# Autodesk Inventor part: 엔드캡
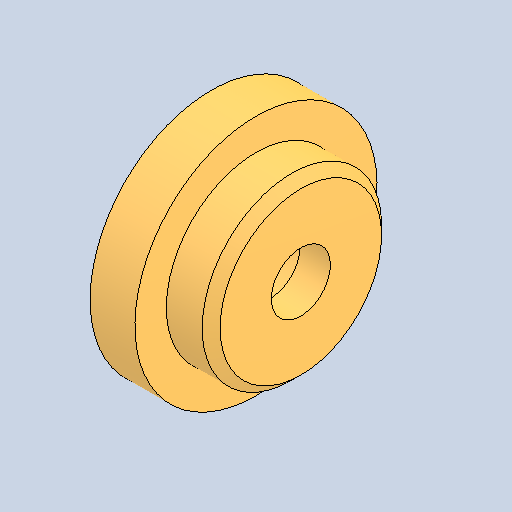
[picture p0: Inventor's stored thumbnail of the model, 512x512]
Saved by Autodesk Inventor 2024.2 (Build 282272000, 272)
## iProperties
Created: 2026-01
Part Number: 엔드캡
Material: 강철, 연강
Document SubType Name: Modeling
Designer: home
Density: 7.85 g/cm^3
Appearance: 기본값
Author: jhkim
Sending System: Autodesk Inventor 2026
Preprocessor: ST-DEVELOPER v20.1
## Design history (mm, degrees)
feature "솔리드1"
node "솔리드2"
